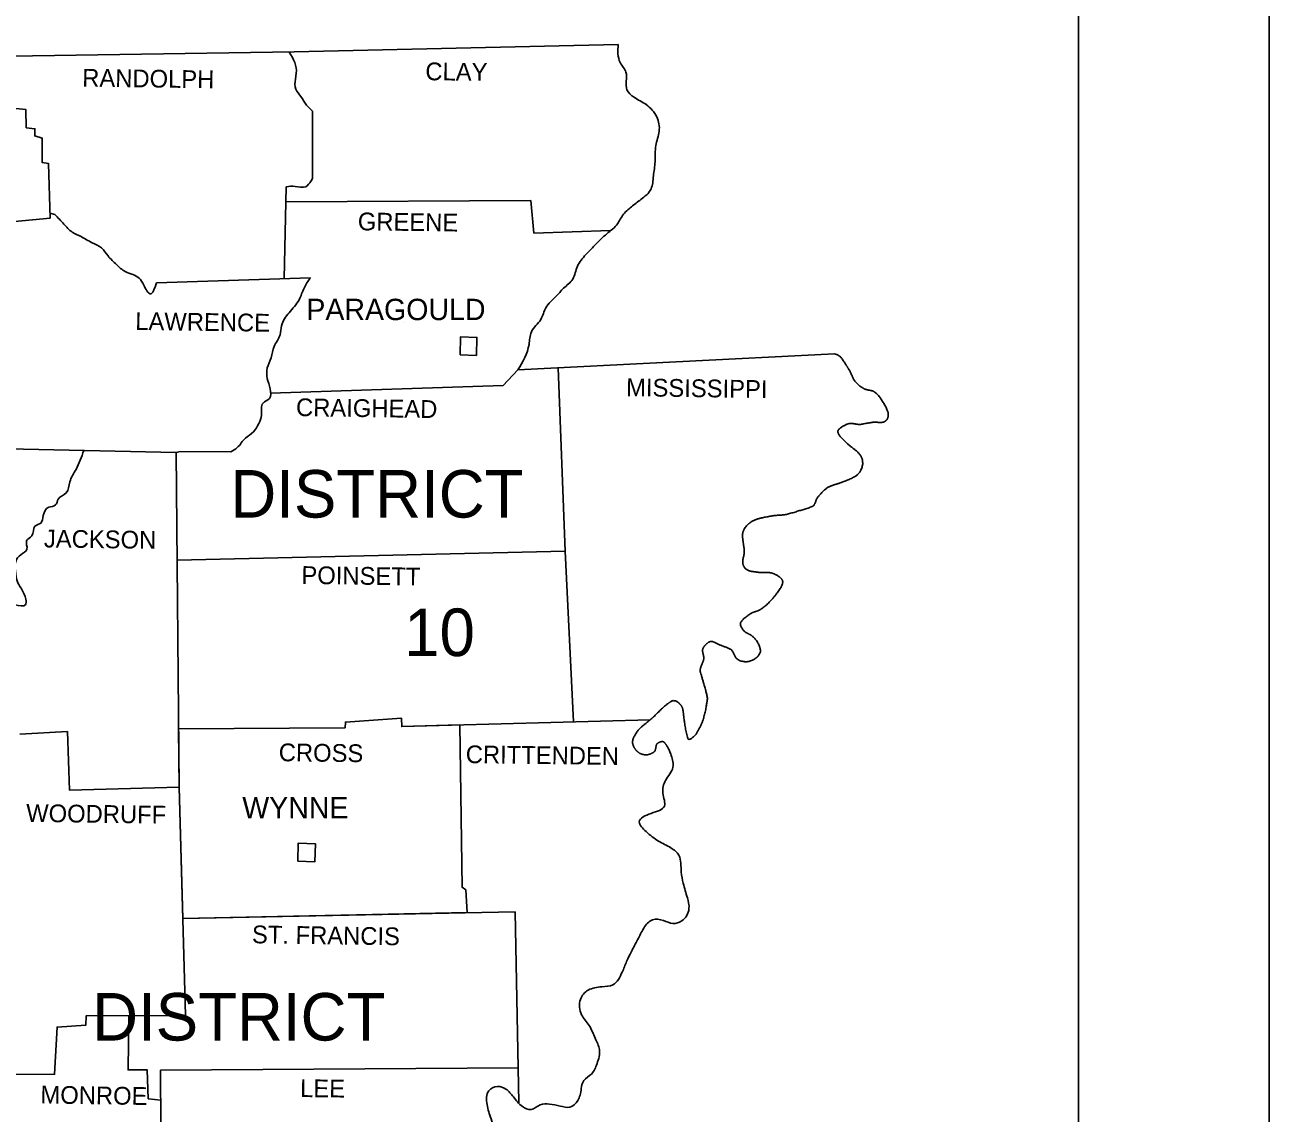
# Model space of a CAD drawing. Extents: x -0.68 to 1.92, y 0 to 0.95.
# Drawn here: x 1.2805 to 1.4167, y 0.703 to 0.8221 of the extents above; entities that cross this region are included whole.
import ezdxf

# ---------------------------------------------------------------- set-up
doc = ezdxf.new("R2010")
doc.units = 0
for name, color, linetype in [('Default', 7, 'Continuous'), ('DSN_DRFT_Guideline-No-Plot', 7, 'Continuous'), ('SHET_Border-Lines', 7, 'Continuous'), ('SHET_Stamp-Seal', 7, 'Continuous')]:
    doc.layers.add(name, color=color, linetype=linetype)

msp = doc.modelspace()

# ---------------------------------------------------------------- linework, layer by layer
at = {"layer": 'Default'}
for p, q in [((1.30981, 0.81849), (1.30946, 0.81908)), ((1.31179, 0.81284), (1.31202, 0.81262)), ((1.31186, 0.80498), (1.31202, 0.80525)), ((1.28383, 0.80129), (1.28329, 0.80145)), ((1.31176, 0.79437), (1.31178, 0.79439)), ((1.27998, 0.74446), (1.28519, 0.74474)), ((1.29742, 0.73864), (1.29736, 0.74504)), ((1.29782, 0.72429), (1.29742, 0.73864)), ((1.32894, 0.72492), (1.29782, 0.72429))]:
    msp.add_line(p, q, dxfattribs=at)
for points in [[(1.09511, 0.81784), (1.16886, 0.81779), (1.23365, 0.81792), (1.31002, 0.81909), (1.34545, 0.81992)], [(1.27561, 0.81856), (1.27545, 0.81717), (1.27636, 0.81704), (1.27628, 0.81652), (1.27735, 0.81628), (1.27742, 0.81553), (1.27794, 0.81522), (1.27807, 0.81304), (1.28066, 0.81278), (1.28069, 0.81079), (1.28165, 0.81068), (1.28162, 0.8099), (1.28245, 0.80965), (1.28243, 0.807), (1.28313, 0.80687), (1.28331, 0.80091), (1.27945, 0.80054), (1.2795, 0.79927), (1.27833, 0.79919), (1.27872, 0.77567), (1.29711, 0.77526), (1.29742, 0.73864), (1.28541, 0.73833), (1.28519, 0.74474)], [(1.31202, 0.81262), (1.31202, 0.80525)], [(1.30892, 0.7943), (1.30914, 0.80435)], [(1.3091, 0.80269), (1.33588, 0.80282), (1.33624, 0.79927), (1.3446, 0.79956)], [(1.29495, 0.79383), (1.31178, 0.79439)], [(1.33448, 0.78431), (1.36913, 0.78605)], [(1.30741, 0.78176), (1.33287, 0.7826), (1.33448, 0.78431)], [(1.33888, 0.78453), (1.33964, 0.76447), (1.34056, 0.74579)], [(1.30307, 0.77533), (1.29752, 0.77536), (1.29711, 0.77526)], [(1.33964, 0.76447), (1.29721, 0.7635)], [(1.29736, 0.74504), (1.31557, 0.74515), (1.31562, 0.74577), (1.32174, 0.74621), (1.32177, 0.74528), (1.34896, 0.74602)], [(1.29736, 0.74504), (1.31557, 0.74515), (1.31562, 0.74577), (1.32174, 0.74621), (1.32177, 0.74528), (1.32812, 0.74545)], [(1.32812, 0.74545), (1.32838, 0.72769), (1.32877, 0.72741), (1.32894, 0.72492)], [(1.32812, 0.74545), (1.32838, 0.72769), (1.32877, 0.72741), (1.32894, 0.72492)], [(1.29742, 0.73864), (1.29812, 0.71366), (1.28725, 0.71361), (1.2872, 0.7126), (1.28406, 0.71239), (1.2838, 0.70723), (1.27948, 0.7072)], [(1.29782, 0.72429), (1.33419, 0.72502)], [(1.33419, 0.72502), (1.33457, 0.70412)], [(1.29192, 0.71363), (1.29184, 0.7077), (1.29394, 0.7077), (1.29405, 0.70456), (1.29542, 0.7044)], [(1.29727, 0.6672), (1.30154, 0.66747), (1.30152, 0.67671), (1.29814, 0.67697), (1.29833, 0.69507), (1.29547, 0.69548), (1.2954, 0.70767), (1.3345, 0.70793)]]:
    msp.add_lwpolyline(points, dxfattribs=at)
for points in [[(1.32815, 0.78594), (1.3282, 0.78791), (1.32999, 0.78786), (1.32994, 0.78589)], [(1.31041, 0.73055), (1.31046, 0.73252), (1.31233, 0.73246), (1.31228, 0.73049)], [(1.31041, 0.73055), (1.31046, 0.73252), (1.31233, 0.73246), (1.31228, 0.73049)]]:
    msp.add_lwpolyline(points, close=True, dxfattribs=at)
for points in [[(1.34545, 0.81992), (1.34568, 0.81792), (1.3463, 0.81688), (1.34641, 0.81496), (1.34719, 0.81413), (1.34851, 0.81333), (1.34968, 0.81198), (1.34994, 0.81042), (1.34957, 0.80884), (1.34949, 0.80708), (1.34931, 0.80552), (1.34905, 0.8041), (1.34794, 0.80295), (1.3469, 0.80215), (1.34594, 0.80119), (1.34527, 0.80015), (1.34405, 0.79906), (1.34288, 0.79792), (1.34192, 0.79691), (1.34099, 0.79564), (1.34049, 0.79424), (1.33948, 0.79323), (1.33865, 0.79232), (1.33754, 0.7911), (1.33699, 0.78983), (1.33596, 0.78846), (1.3357, 0.78708), (1.33448, 0.78431)], [(1.30981, 0.81849), (1.31023, 0.81737), (1.31015, 0.81613), (1.31018, 0.81501), (1.31075, 0.81421), (1.31137, 0.81325), (1.31179, 0.81284)], [(1.31186, 0.80498), (1.31127, 0.80435), (1.3101, 0.80438), (1.30914, 0.80435)], [(1.28383, 0.80129), (1.28481, 0.80026), (1.28572, 0.79938), (1.28671, 0.79888), (1.2879, 0.79821), (1.28894, 0.79764), (1.28964, 0.79678), (1.29057, 0.79582), (1.29153, 0.79507), (1.29306, 0.79434), (1.29355, 0.79357), (1.29425, 0.79261), (1.29495, 0.79383)], [(1.31176, 0.79437), (1.31109, 0.79325), (1.31054, 0.79198), (1.30945, 0.79056), (1.30862, 0.78913), (1.30847, 0.78815), (1.30782, 0.78687), (1.30748, 0.78563), (1.30707, 0.78451), (1.30707, 0.78337), (1.30738, 0.78223), (1.3073, 0.78117), (1.3066, 0.78068), (1.30644, 0.77935), (1.30613, 0.77845), (1.30554, 0.77751), (1.30468, 0.77684), (1.30377, 0.7758), (1.30307, 0.77533)], [(1.28698, 0.77548), (1.28614, 0.77342), (1.28546, 0.77204), (1.28507, 0.77085), (1.28419, 0.77017), (1.28391, 0.76952), (1.28315, 0.76927), (1.28256, 0.76836), (1.2823, 0.76755), (1.28165, 0.76719), (1.28131, 0.76615), (1.28074, 0.76561), (1.28077, 0.7647), (1.28009, 0.76408), (1.27955, 0.76335), (1.27952, 0.76232), (1.27978, 0.76102), (1.28025, 0.76021), (1.28064, 0.75923), (1.28061, 0.75858), (1.27947, 0.75858), (1.27849, 0.75843)], [(1.35126, 0.74211), (1.35144, 0.74082), (1.35064, 0.73939), (1.35035, 0.73799), (1.35051, 0.73656), (1.34905, 0.73578), (1.34776, 0.73485), (1.34851, 0.73379), (1.34986, 0.73275), (1.35123, 0.732), (1.35209, 0.73119), (1.35235, 0.72935), (1.35258, 0.72813), (1.35302, 0.72653), (1.3532, 0.72536), (1.3524, 0.72401), (1.35144, 0.72373), (1.3504, 0.72406), (1.34921, 0.72414), (1.34825, 0.72321), (1.34758, 0.72196), (1.3469, 0.72066), (1.34638, 0.71958), (1.34589, 0.71841), (1.34488, 0.71703), (1.34366, 0.7168), (1.34218, 0.71644), (1.34132, 0.71543), (1.34145, 0.71374), (1.34228, 0.71257), (1.34293, 0.71117), (1.3434, 0.70993), (1.34314, 0.7084), (1.34252, 0.70726), (1.34171, 0.70656), (1.34132, 0.7051), (1.34075, 0.70401), (1.34018, 0.70365), (1.33909, 0.70376), (1.33793, 0.70396), (1.33692, 0.70389), (1.33593, 0.70337), (1.33497, 0.7037), (1.33399, 0.70477), (1.33318, 0.7056), (1.33225, 0.70591), (1.33129, 0.70542), (1.33111, 0.70391), (1.33155, 0.70236), (1.33199, 0.70025), (1.33157, 0.69901), (1.33142, 0.69688)]]:
    msp.add_spline(points, degree=3, dxfattribs=at)
msp.add_open_spline([(1.36913, 0.78605), (1.3693, 0.78602), (1.36947, 0.78595), (1.36962, 0.78584), (1.36978, 0.78572), (1.3699, 0.78558), (1.37001, 0.78543), (1.37012, 0.78526), (1.37024, 0.78509), (1.37034, 0.78492), (1.37039, 0.78483), (1.37045, 0.78474), (1.3705, 0.78466), (1.37055, 0.78458), (1.3706, 0.78449), (1.37066, 0.78441), (1.37073, 0.7843), (1.37079, 0.78419), (1.37085, 0.78407), (1.3709, 0.78395), (1.37095, 0.78383), (1.37101, 0.78371), (1.37106, 0.7836), (1.37112, 0.78348), (1.37117, 0.78336), (1.37123, 0.78325), (1.3713, 0.78314), (1.37138, 0.78304), (1.37165, 0.78271), (1.37197, 0.78246), (1.37234, 0.78226), (1.37243, 0.78221), (1.37253, 0.78217), (1.37263, 0.78214), (1.37273, 0.78212), (1.37283, 0.7821), (1.37293, 0.78208), (1.37303, 0.78206), (1.37314, 0.78204), (1.37324, 0.78201), (1.37334, 0.78198), (1.37343, 0.78194), (1.37351, 0.78187), (1.37388, 0.78158), (1.37414, 0.78123), (1.37439, 0.78083), (1.37463, 0.78046), (1.37483, 0.78009), (1.37496, 0.77967), (1.37499, 0.77958), (1.375, 0.77949), (1.375, 0.77941), (1.375, 0.77932), (1.37499, 0.77923), (1.37497, 0.77913), (1.37494, 0.77904), (1.37491, 0.77896), (1.37486, 0.77888), (1.37483, 0.77884), (1.3748, 0.7788), (1.37477, 0.77877), (1.37475, 0.77875), (1.37473, 0.77874), (1.37471, 0.77872), (1.37469, 0.77871), (1.37467, 0.77869), (1.37465, 0.77868), (1.37455, 0.77862), (1.37444, 0.77858), (1.37433, 0.77856), (1.37422, 0.77855), (1.37411, 0.77855), (1.374, 0.77855), (1.37389, 0.77856), (1.37379, 0.77858), (1.37368, 0.77858), (1.37362, 0.77859), (1.37357, 0.77859), (1.37351, 0.77859), (1.37346, 0.77859), (1.37341, 0.77858), (1.37335, 0.77858), (1.37312, 0.77854), (1.37289, 0.7785), (1.37265, 0.77846), (1.37242, 0.77842), (1.37219, 0.77838), (1.37195, 0.77834), (1.37184, 0.77832), (1.37173, 0.77833), (1.37162, 0.77835), (1.37151, 0.77836), (1.37139, 0.77839), (1.37128, 0.77841), (1.37117, 0.77842), (1.37106, 0.77844), (1.37094, 0.77845), (1.37089, 0.77845), (1.37083, 0.77844), (1.37077, 0.77844), (1.37072, 0.77843), (1.37066, 0.77841), (1.3706, 0.77839), (1.37047, 0.77835), (1.37035, 0.77829), (1.37022, 0.77823), (1.37009, 0.77817), (1.36996, 0.77809), (1.36984, 0.77801), (1.36974, 0.77794), (1.36965, 0.77786), (1.36957, 0.77776), (1.36953, 0.77771), (1.36951, 0.77767), (1.3695, 0.77762), (1.36949, 0.7776), (1.36949, 0.77758), (1.36949, 0.77755), (1.36948, 0.77753), (1.36948, 0.77751), (1.36949, 0.77749), (1.36952, 0.77738), (1.36956, 0.77728), (1.36963, 0.77718), (1.36971, 0.77707), (1.36979, 0.77697), (1.36988, 0.77687), (1.37008, 0.77667), (1.37029, 0.77646), (1.3705, 0.77627), (1.37061, 0.77617), (1.37072, 0.77607), (1.37083, 0.77598), (1.37094, 0.77589), (1.37106, 0.7758), (1.37117, 0.77571), (1.37128, 0.77562), (1.37139, 0.77553), (1.37151, 0.77544), (1.37162, 0.77535), (1.37172, 0.77524), (1.37182, 0.77513), (1.3719, 0.77504), (1.37196, 0.77494), (1.37202, 0.77484), (1.37207, 0.77474), (1.37211, 0.77463), (1.37215, 0.77452), (1.37218, 0.77441), (1.37219, 0.7743), (1.3722, 0.77419), (1.37221, 0.77409), (1.37221, 0.77399), (1.37219, 0.77388), (1.37214, 0.77365), (1.37206, 0.77344), (1.37194, 0.77323), (1.37188, 0.77312), (1.3718, 0.77302), (1.37172, 0.77293), (1.37163, 0.77284), (1.37154, 0.77276), (1.37143, 0.77269), (1.37121, 0.77255), (1.37097, 0.77242), (1.37073, 0.77232), (1.37049, 0.77223), (1.37025, 0.77213), (1.37001, 0.77204), (1.36989, 0.772), (1.36977, 0.77195), (1.36965, 0.77191), (1.36952, 0.77187), (1.3694, 0.77183), (1.36928, 0.77179), (1.36916, 0.77175), (1.36904, 0.77171), (1.36891, 0.77167), (1.36879, 0.77163), (1.36867, 0.77158), (1.36856, 0.77152), (1.36843, 0.77146), (1.36831, 0.77139), (1.3682, 0.7713), (1.36809, 0.77122), (1.36798, 0.77113), (1.36788, 0.77103), (1.36778, 0.77093), (1.36769, 0.77082), (1.36759, 0.77072), (1.3675, 0.77062), (1.3674, 0.77051), (1.36731, 0.77041), (1.36724, 0.77033), (1.36719, 0.77024), (1.36715, 0.77014), (1.36711, 0.77004), (1.36708, 0.76994), (1.36704, 0.76984), (1.367, 0.76974), (1.36696, 0.76965), (1.36691, 0.76956), (1.36685, 0.76948), (1.36678, 0.76941), (1.36669, 0.76937), (1.36646, 0.76927), (1.36623, 0.76918), (1.36599, 0.76911), (1.36576, 0.76904), (1.36552, 0.76897), (1.36529, 0.7689), (1.36505, 0.76883), (1.36481, 0.76875), (1.36457, 0.76868), (1.36432, 0.76861), (1.36408, 0.76854), (1.36384, 0.76849), (1.36373, 0.76846), (1.36362, 0.76845), (1.36351, 0.76844), (1.36341, 0.76843), (1.3633, 0.76842), (1.36319, 0.76841), (1.36308, 0.7684), (1.36297, 0.7684), (1.36286, 0.76839), (1.36276, 0.76838), (1.36265, 0.76837), (1.36254, 0.76836), (1.3623, 0.76833), (1.36206, 0.76829), (1.36182, 0.76824), (1.36159, 0.7682), (1.36135, 0.76815), (1.36111, 0.7681), (1.36098, 0.76807), (1.36085, 0.76804), (1.36073, 0.768), (1.3606, 0.76796), (1.36048, 0.76791), (1.36036, 0.76786), (1.36023, 0.7678), (1.36012, 0.76774), (1.36, 0.76766), (1.35994, 0.76763), (1.35989, 0.76758), (1.35983, 0.76754), (1.35977, 0.7675), (1.35972, 0.76745), (1.35966, 0.7674), (1.35949, 0.76724), (1.35934, 0.76705), (1.35922, 0.76684), (1.35917, 0.76674), (1.35913, 0.76664), (1.35911, 0.76653), (1.35908, 0.76642), (1.35906, 0.76631), (1.35906, 0.76621), (1.35906, 0.76607), (1.35907, 0.76592), (1.35908, 0.76578), (1.3591, 0.76564), (1.35912, 0.7655), (1.35914, 0.76536), (1.35916, 0.76522), (1.35918, 0.76508), (1.3592, 0.76494), (1.35922, 0.7648), (1.35924, 0.76466), (1.35925, 0.76452), (1.35925, 0.76437), (1.35923, 0.76423), (1.35921, 0.76408), (1.35919, 0.76393), (1.35914, 0.76379), (1.35912, 0.76364), (1.35909, 0.76349), (1.35908, 0.76334), (1.35908, 0.76319), (1.35909, 0.76312), (1.3591, 0.76305), (1.35912, 0.76297), (1.35913, 0.76294), (1.35915, 0.7629), (1.35916, 0.76287), (1.35918, 0.76283), (1.3592, 0.76279), (1.35922, 0.76276), (1.35929, 0.76263), (1.35939, 0.76253), (1.35951, 0.76245), (1.35963, 0.76237), (1.35976, 0.76232), (1.35989, 0.76229), (1.36003, 0.76226), (1.36017, 0.76224), (1.36031, 0.76222), (1.36045, 0.7622), (1.36058, 0.76218), (1.36072, 0.76216), (1.36083, 0.76215), (1.36094, 0.76213), (1.36105, 0.76213), (1.36116, 0.76213), (1.36127, 0.76214), (1.36138, 0.76214), (1.3615, 0.76214), (1.36161, 0.76214), (1.36172, 0.76214), (1.36183, 0.76214), (1.36194, 0.76213), (1.36205, 0.76211), (1.36229, 0.76206), (1.36253, 0.76198), (1.36275, 0.76187), (1.36287, 0.76182), (1.36297, 0.76175), (1.36307, 0.76167), (1.36312, 0.76164), (1.36317, 0.76159), (1.36321, 0.76155), (1.36326, 0.76151), (1.3633, 0.76146), (1.36334, 0.76141), (1.3634, 0.76134), (1.36343, 0.76125), (1.36344, 0.76117), (1.36346, 0.76108), (1.36345, 0.76099), (1.36342, 0.7609), (1.36336, 0.76072), (1.36329, 0.76055), (1.36319, 0.7604), (1.36304, 0.76018), (1.3629, 0.75996), (1.36274, 0.75976), (1.36266, 0.75965), (1.36258, 0.75955), (1.36249, 0.75945), (1.36241, 0.75935), (1.36232, 0.75925), (1.36223, 0.75915), (1.36189, 0.75878), (1.36152, 0.75844), (1.36111, 0.75814), (1.36103, 0.75808), (1.36094, 0.75803), (1.36084, 0.75799), (1.36075, 0.75795), (1.36065, 0.75792), (1.36055, 0.75788), (1.36046, 0.75785), (1.36036, 0.75782), (1.36026, 0.75778), (1.36016, 0.75775), (1.36006, 0.7577), (1.35997, 0.75765), (1.35975, 0.75752), (1.35955, 0.75737), (1.35935, 0.75721), (1.35925, 0.75713), (1.35917, 0.75705), (1.35909, 0.75696), (1.35901, 0.75688), (1.35894, 0.75679), (1.35888, 0.75669), (1.35881, 0.75655), (1.35884, 0.75635), (1.35891, 0.7562), (1.359, 0.75603), (1.3591, 0.75586), (1.35925, 0.75573), (1.35932, 0.75566), (1.35939, 0.75559), (1.35948, 0.75554), (1.35957, 0.7555), (1.35966, 0.75545), (1.35974, 0.7554), (1.35983, 0.75536), (1.35991, 0.75531), (1.36, 0.75526), (1.36009, 0.75522), (1.36016, 0.75515), (1.36023, 0.75508), (1.36054, 0.75478), (1.36076, 0.75442), (1.36091, 0.75404), (1.36102, 0.75375), (1.36102, 0.75335), (1.36083, 0.75308), (1.36079, 0.75303), (1.36075, 0.75299), (1.36071, 0.75295), (1.36067, 0.7529), (1.36063, 0.75286), (1.36058, 0.75283), (1.3605, 0.75275), (1.36041, 0.75269), (1.36032, 0.75263), (1.36014, 0.75252), (1.35994, 0.75246), (1.35974, 0.75241), (1.35954, 0.75236), (1.35932, 0.75237), (1.35912, 0.7524), (1.35891, 0.75244), (1.35871, 0.75251), (1.35852, 0.75264), (1.35841, 0.75272), (1.35833, 0.7528), (1.35827, 0.75291), (1.35821, 0.75302), (1.35816, 0.75313), (1.3581, 0.75324), (1.35804, 0.75335), (1.35799, 0.75346), (1.35792, 0.75356), (1.35786, 0.75366), (1.35777, 0.75374), (1.35766, 0.75378), (1.35734, 0.75393), (1.357, 0.75404), (1.35668, 0.75417), (1.35638, 0.75429), (1.35609, 0.75444), (1.3558, 0.75456), (1.35571, 0.75459), (1.35562, 0.7546), (1.35553, 0.75458), (1.35544, 0.75455), (1.35535, 0.75451), (1.35527, 0.75445), (1.35518, 0.75438), (1.3551, 0.75432), (1.35503, 0.75424), (1.35499, 0.75419), (1.35495, 0.75415), (1.35491, 0.7541), (1.35488, 0.75406), (1.35484, 0.75401), (1.35481, 0.75396), (1.35475, 0.75387), (1.3547, 0.75375), (1.35469, 0.75364), (1.35469, 0.75353), (1.3547, 0.75342), (1.35472, 0.75331), (1.35475, 0.7532), (1.35478, 0.7531), (1.3548, 0.75299), (1.35481, 0.75293), (1.35481, 0.75288), (1.35482, 0.75283), (1.35482, 0.75277), (1.35482, 0.75272), (1.35481, 0.75267), (1.35479, 0.75254), (1.35475, 0.75243), (1.35471, 0.75231), (1.35466, 0.75219), (1.3546, 0.75207), (1.35456, 0.75195), (1.35451, 0.75184), (1.35447, 0.75172), (1.35444, 0.7516), (1.35442, 0.75148), (1.35442, 0.75136), (1.35445, 0.75124), (1.35455, 0.75089), (1.35466, 0.75053), (1.35476, 0.75018), (1.35489, 0.7497), (1.35503, 0.74923), (1.35515, 0.74875), (1.35523, 0.7484), (1.35518, 0.74802), (1.35512, 0.74766), (1.35503, 0.74713), (1.35492, 0.7466), (1.35476, 0.74608), (1.35471, 0.74594), (1.35467, 0.7458), (1.35461, 0.74566), (1.35455, 0.74552), (1.35449, 0.74539), (1.35443, 0.74526), (1.35436, 0.74512), (1.35429, 0.74499), (1.35421, 0.74486), (1.35414, 0.74473), (1.35406, 0.7446), (1.35398, 0.74447), (1.35386, 0.74428), (1.35369, 0.74414), (1.3535, 0.74399), (1.35341, 0.74393), (1.35332, 0.7439), (1.35323, 0.74388), (1.3532, 0.74387), (1.35317, 0.74387), (1.35313, 0.7439), (1.3531, 0.74392), (1.35308, 0.74395), (1.35307, 0.74398), (1.35299, 0.74426), (1.35291, 0.74455), (1.35286, 0.74484), (1.35281, 0.74513), (1.35275, 0.74542), (1.35271, 0.74572), (1.35268, 0.74595), (1.35265, 0.74618), (1.35262, 0.74642), (1.35261, 0.74653), (1.3526, 0.74665), (1.35258, 0.74677), (1.35257, 0.74689), (1.35255, 0.747), (1.35253, 0.74712), (1.35251, 0.7472), (1.35249, 0.74728), (1.35246, 0.74735), (1.35242, 0.74743), (1.35239, 0.7475), (1.35234, 0.74757), (1.35229, 0.74764), (1.35224, 0.7477), (1.35218, 0.74777), (1.35212, 0.74783), (1.35206, 0.74789), (1.35198, 0.74795), (1.35187, 0.74804), (1.35174, 0.74809), (1.3516, 0.7481), (1.35148, 0.74812), (1.35134, 0.74809), (1.35123, 0.74803), (1.35115, 0.74797), (1.35107, 0.74792), (1.35099, 0.74786), (1.35091, 0.7478), (1.35083, 0.74775), (1.35075, 0.74768), (1.35059, 0.74756), (1.35044, 0.74744), (1.3503, 0.7473), (1.35012, 0.74713), (1.34994, 0.74695), (1.34977, 0.74678), (1.34959, 0.74661), (1.34941, 0.74643), (1.34923, 0.74626), (1.34913, 0.74616), (1.34902, 0.74607), (1.34891, 0.74598), (1.3488, 0.74589), (1.34869, 0.7458), (1.34858, 0.74571), (1.34847, 0.74562), (1.34836, 0.74553), (1.34824, 0.74544), (1.34813, 0.74534), (1.34802, 0.74525), (1.34791, 0.74515), (1.34773, 0.74498), (1.34758, 0.74479), (1.34744, 0.74459), (1.34737, 0.74449), (1.34731, 0.74439), (1.34726, 0.74429), (1.3472, 0.74419), (1.34715, 0.74409), (1.34711, 0.74398), (1.34706, 0.74387), (1.34704, 0.74375), (1.34703, 0.74364), (1.34703, 0.74351), (1.34704, 0.74339), (1.34709, 0.74327), (1.34713, 0.74313), (1.34718, 0.74301), (1.34726, 0.7429), (1.3473, 0.74283), (1.34734, 0.74278), (1.34739, 0.74272), (1.34741, 0.74269), (1.34744, 0.74266), (1.34747, 0.74263), (1.34749, 0.74261), (1.34752, 0.74258), (1.34755, 0.74255), (1.34763, 0.74248), (1.34771, 0.74242), (1.3478, 0.74237), (1.34788, 0.74232), (1.34797, 0.74228), (1.34805, 0.74225), (1.34814, 0.74223), (1.34822, 0.74221), (1.34831, 0.7422), (1.34839, 0.74219), (1.34848, 0.74219), (1.34856, 0.74219), (1.34863, 0.74219), (1.34869, 0.7422), (1.34876, 0.74221), (1.34882, 0.74223), (1.34889, 0.74225), (1.34895, 0.74227), (1.34902, 0.7423), (1.34908, 0.74233), (1.34914, 0.74236), (1.34921, 0.74239), (1.34928, 0.74243), (1.34934, 0.74248), (1.34941, 0.74253), (1.34947, 0.7426), (1.3495, 0.74268), (1.34953, 0.74276), (1.34955, 0.74285), (1.34956, 0.74294), (1.34958, 0.74302), (1.34959, 0.74311), (1.34961, 0.7432), (1.34963, 0.74328), (1.34967, 0.74335), (1.34973, 0.74341), (1.34978, 0.74346), (1.34984, 0.7435), (1.3499, 0.74353), (1.34997, 0.74357), (1.35005, 0.74359), (1.35012, 0.74361), (1.35019, 0.74363), (1.35027, 0.74364), (1.35034, 0.74363), (1.3504, 0.74361), (1.35046, 0.74359), (1.35051, 0.74354), (1.35055, 0.74349), (1.35059, 0.74344), (1.35063, 0.74338), (1.35067, 0.74333), (1.35071, 0.74327), (1.35075, 0.74322), (1.35082, 0.74311), (1.35089, 0.74299), (1.35095, 0.74287), (1.35108, 0.74263), (1.35117, 0.74237), (1.35126, 0.74211)], degree=3, dxfattribs=at)
at = {"layer": 'DSN_DRFT_Guideline-No-Plot'}
msp.add_lwpolyline([(0, 0), (1.41667, 0), (1.41667, 0.91667), (0, 0.91667)], close=True, dxfattribs=at)
at = {"layer": 'SHET_Border-Lines'}
msp.add_lwpolyline([(0.02083, 0.02083), (1.39583, 0.02083), (1.39583, 0.89583), (0.02083, 0.89583)], close=True, dxfattribs=at)
at = {"layer": 'SHET_Stamp-Seal'}
msp.add_line((1.32192, 0.78946), (1.32192, 0.78946), dxfattribs=at)

# ---------------------------------------------------------------- texts
at = {"layer": 'Default'}
for s, height, rotation, p in [('RANDOLPH', 0.001945, 359.2573, (1.28681, 0.8153)), ('CLAY', 0.001945, 359.3364, (1.32435, 0.816)), ('GREENE', 0.001945, 359.2711, (1.31696, 0.79958)), ('LAWRENCE', 0.001945, 359.2655, (1.29261, 0.78867)), ('MISSISSIPPI', 0.0019451, 359.2098, (1.34631, 0.78143)), ('CRAIGHEAD', 0.001945, 359.1888, (1.3102, 0.77925)), ('JACKSON', 0.001945, 359.2575, (1.28262, 0.76488)), ('POINSETT', 0.001945, 359.1979, (1.31079, 0.76089)), ('CROSS', 0.001945, 359.3097, (1.30831, 0.74149)), ('CRITTENDEN', 0.001945, 359.2782, (1.32877, 0.74128)), ('WOODRUFF', 0.001945, 359.2708, (1.28068, 0.73485)), ('ST. FRANCIS', 0.0019451, 359.1956, (1.30538, 0.72157)), ('LEE', 0.001945, 359.3634, (1.31065, 0.70474)), ('MONROE', 0.001945, 359.1697, (1.28224, 0.70404))]:
    msp.add_text(s, height=height, rotation=rotation, dxfattribs=at).set_placement(p)
for s, height, p in [('PARAGOULD', 0.002334, (1.31134, 0.78975)), ('DISTRICT', 0.005203, (1.30302, 0.76814)), ('10', 0.005203, (1.32204, 0.75299)), ('WYNNE', 0.002334, (1.30433, 0.73524)), ('DISTRICT', 0.005203, (1.2879, 0.71092))]:
    msp.add_text(s, height=height, dxfattribs=at).set_placement(p)

doc.saveas('drawing.dxf')
